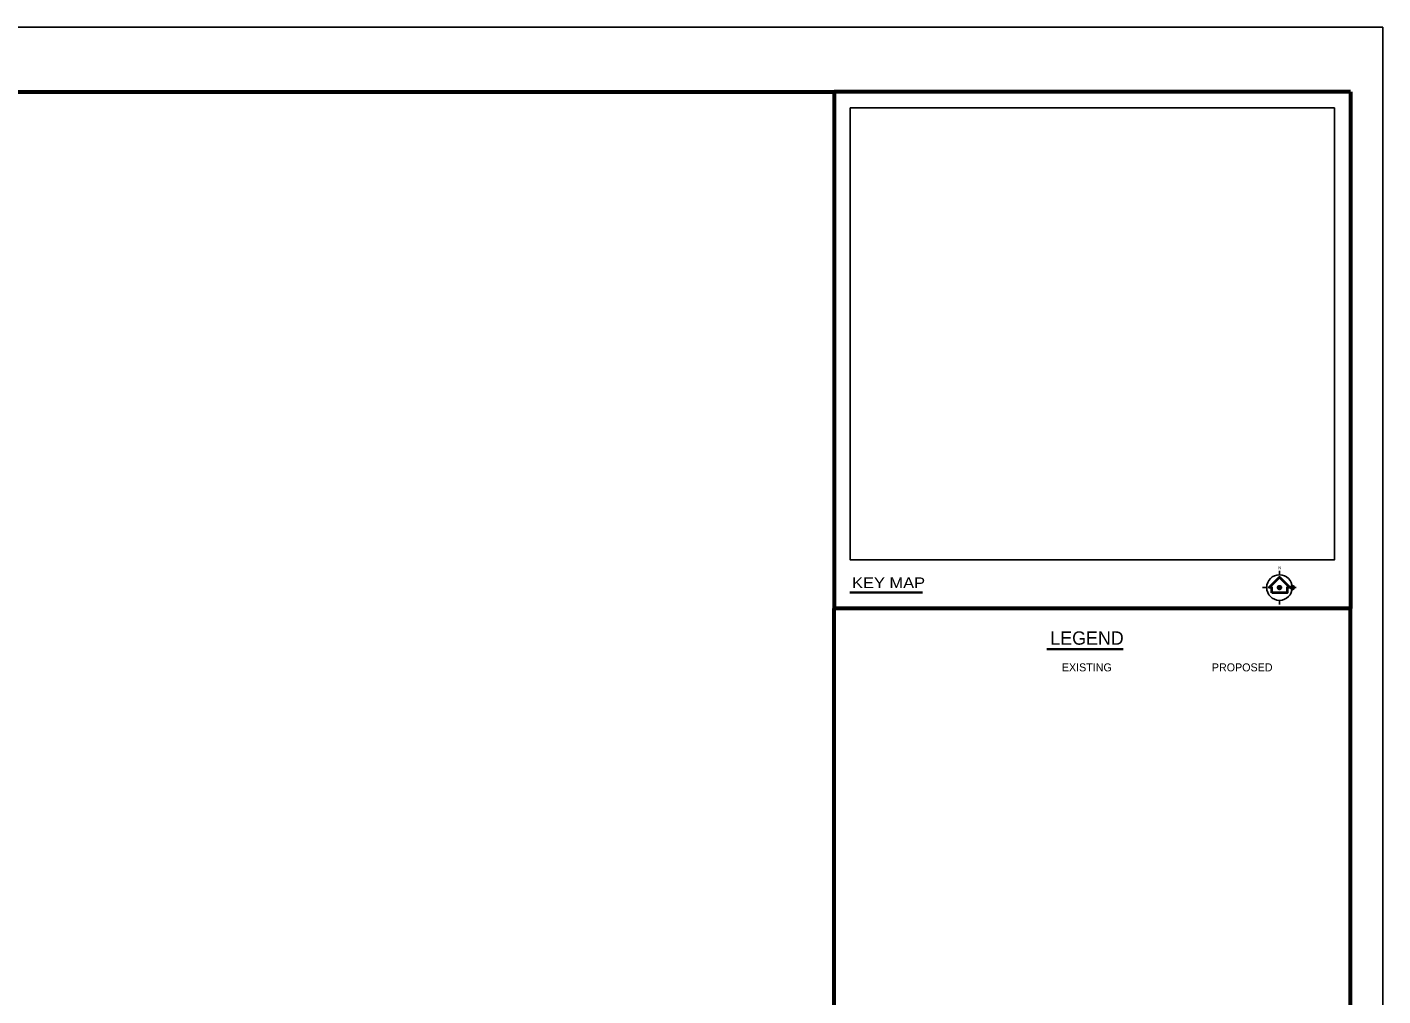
# Model space of a CAD drawing. Extents: x -862045 to -857845, y -1798003 to -1795003.
# Drawn here: x -859945 to -857845, y -1796503 to -1795003 of the extents above; entities that cross this region are included whole.
import ezdxf
from ezdxf.enums import TextEntityAlignment as Align

# ---------------------------------------------------------------- set-up
doc = ezdxf.new("R2010")
doc.units = 0
doc.header["$LTSCALE"] = 5
doc.header["$PDMODE"] = 32
doc.header["$PDSIZE"] = 2.5
for name, color, linetype, lineweight in [('1', 7, 'Continuous', 60), ('2', 7, 'Continuous', 25), ('5', 7, 'Continuous', 25)]:
    doc.layers.add(name, color=color, linetype=linetype, lineweight=lineweight)

msp = doc.modelspace()

# ---------------------------------------------------------------- linework, layer by layer
at = {"layer": '1'}
for p, q in [((-861895.231, -1795102.742), (-858695.231, -1795102.742)), ((-858695.231, -1795102.742), (-858695.231, -1795902.742)), ((-857895.231, -1795102.742), (-858695.231, -1795102.742)), ((-857895.231, -1795102.742), (-857895.231, -1795902.742)), ((-857895.231, -1795902.742), (-858695.231, -1795902.742)), ((-858695.231, -1797902.742), (-858695.231, -1795902.742))]:
    msp.add_line(p, q, dxfattribs=at)
at = {"layer": '1', "lineweight": 25}
for p, q in [((-858005.417, -1795850.731), (-858005.417, -1795844.386)), ((-858025.214, -1795870.511), (-858031.547, -1795870.511)), ((-857979.31, -1795870.511), (-857985.643, -1795870.511)), ((-858005.417, -1795890.297), (-858005.417, -1795896.645))]:
    msp.add_line(p, q, dxfattribs=at)
at = {"layer": '1', "lineweight": 35}
for p, q in [((-858671.091, -1795878.311), (-858558.264, -1795878.311)), ((-858365.796, -1795966.052), (-858247.505, -1795966.052))]:
    msp.add_line(p, q, dxfattribs=at)
at = {"layer": '1', "lineweight": 40}
msp.add_lwpolyline([(-858017.479, -1795878.563), (-858017.479, -1795870.511), (-858021.502, -1795870.511), (-858005.417, -1795854.437), (-857989.339, -1795870.511), (-857993.362, -1795870.511), (-857993.362, -1795878.563)], close=True, dxfattribs=at)
at = {"layer": '1'}
msp.add_lwpolyline([(-858695.231, -1797902.742), (-857895.231, -1797902.742), (-857895.231, -1795902.742)], dxfattribs=at)
at = {"layer": '1', "lineweight": 25}
msp.add_circle((-858005.426, -1795870.511), 19.783, dxfattribs=at)
at = {"layer": '1'}
for p in [(-858005.428, -1795870.51), (-857985.324, -1795870.511)]:
    msp.add_point(p, dxfattribs=at)
at = {"layer": '2'}
for p, q in [((-857845.231, -1795002.742), (-862045.231, -1795002.742)), ((-857845.231, -1798002.742), (-857845.231, -1795002.742))]:
    msp.add_line(p, q, dxfattribs=at)
at = {"layer": '5'}
msp.add_lwpolyline([(-858670.231, -1795127.742), (-857920.231, -1795127.742), (-857920.231, -1795827.742), (-858670.231, -1795827.742)], close=True, dxfattribs=at)

# ---------------------------------------------------------------- texts
at = {"layer": '1'}
for s, height, width, p in [('KEY MAP', 16.54, 1.15, (-858667.44, -1795871.38)), ('N', 4.75, 0.7, (-858007.007, -1795842.541))]:
    msp.add_text(s, height=height, dxfattribs=dict(at, width=width)).set_placement(p)
for s, height, p in [('LEGEND', 20.67, (-858303.507, -1795959.019)), ('EXISTING', 12.4, (-858303.812, -1796000.301)), ('PROPOSED', 12.4, (-858063.148, -1796000.301))]:
    msp.add_text(s, height=height, dxfattribs=at).set_placement(p, align=Align.CENTER)

doc.saveas('drawing.dxf')
